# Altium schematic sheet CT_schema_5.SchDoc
size 578 x 363 mm
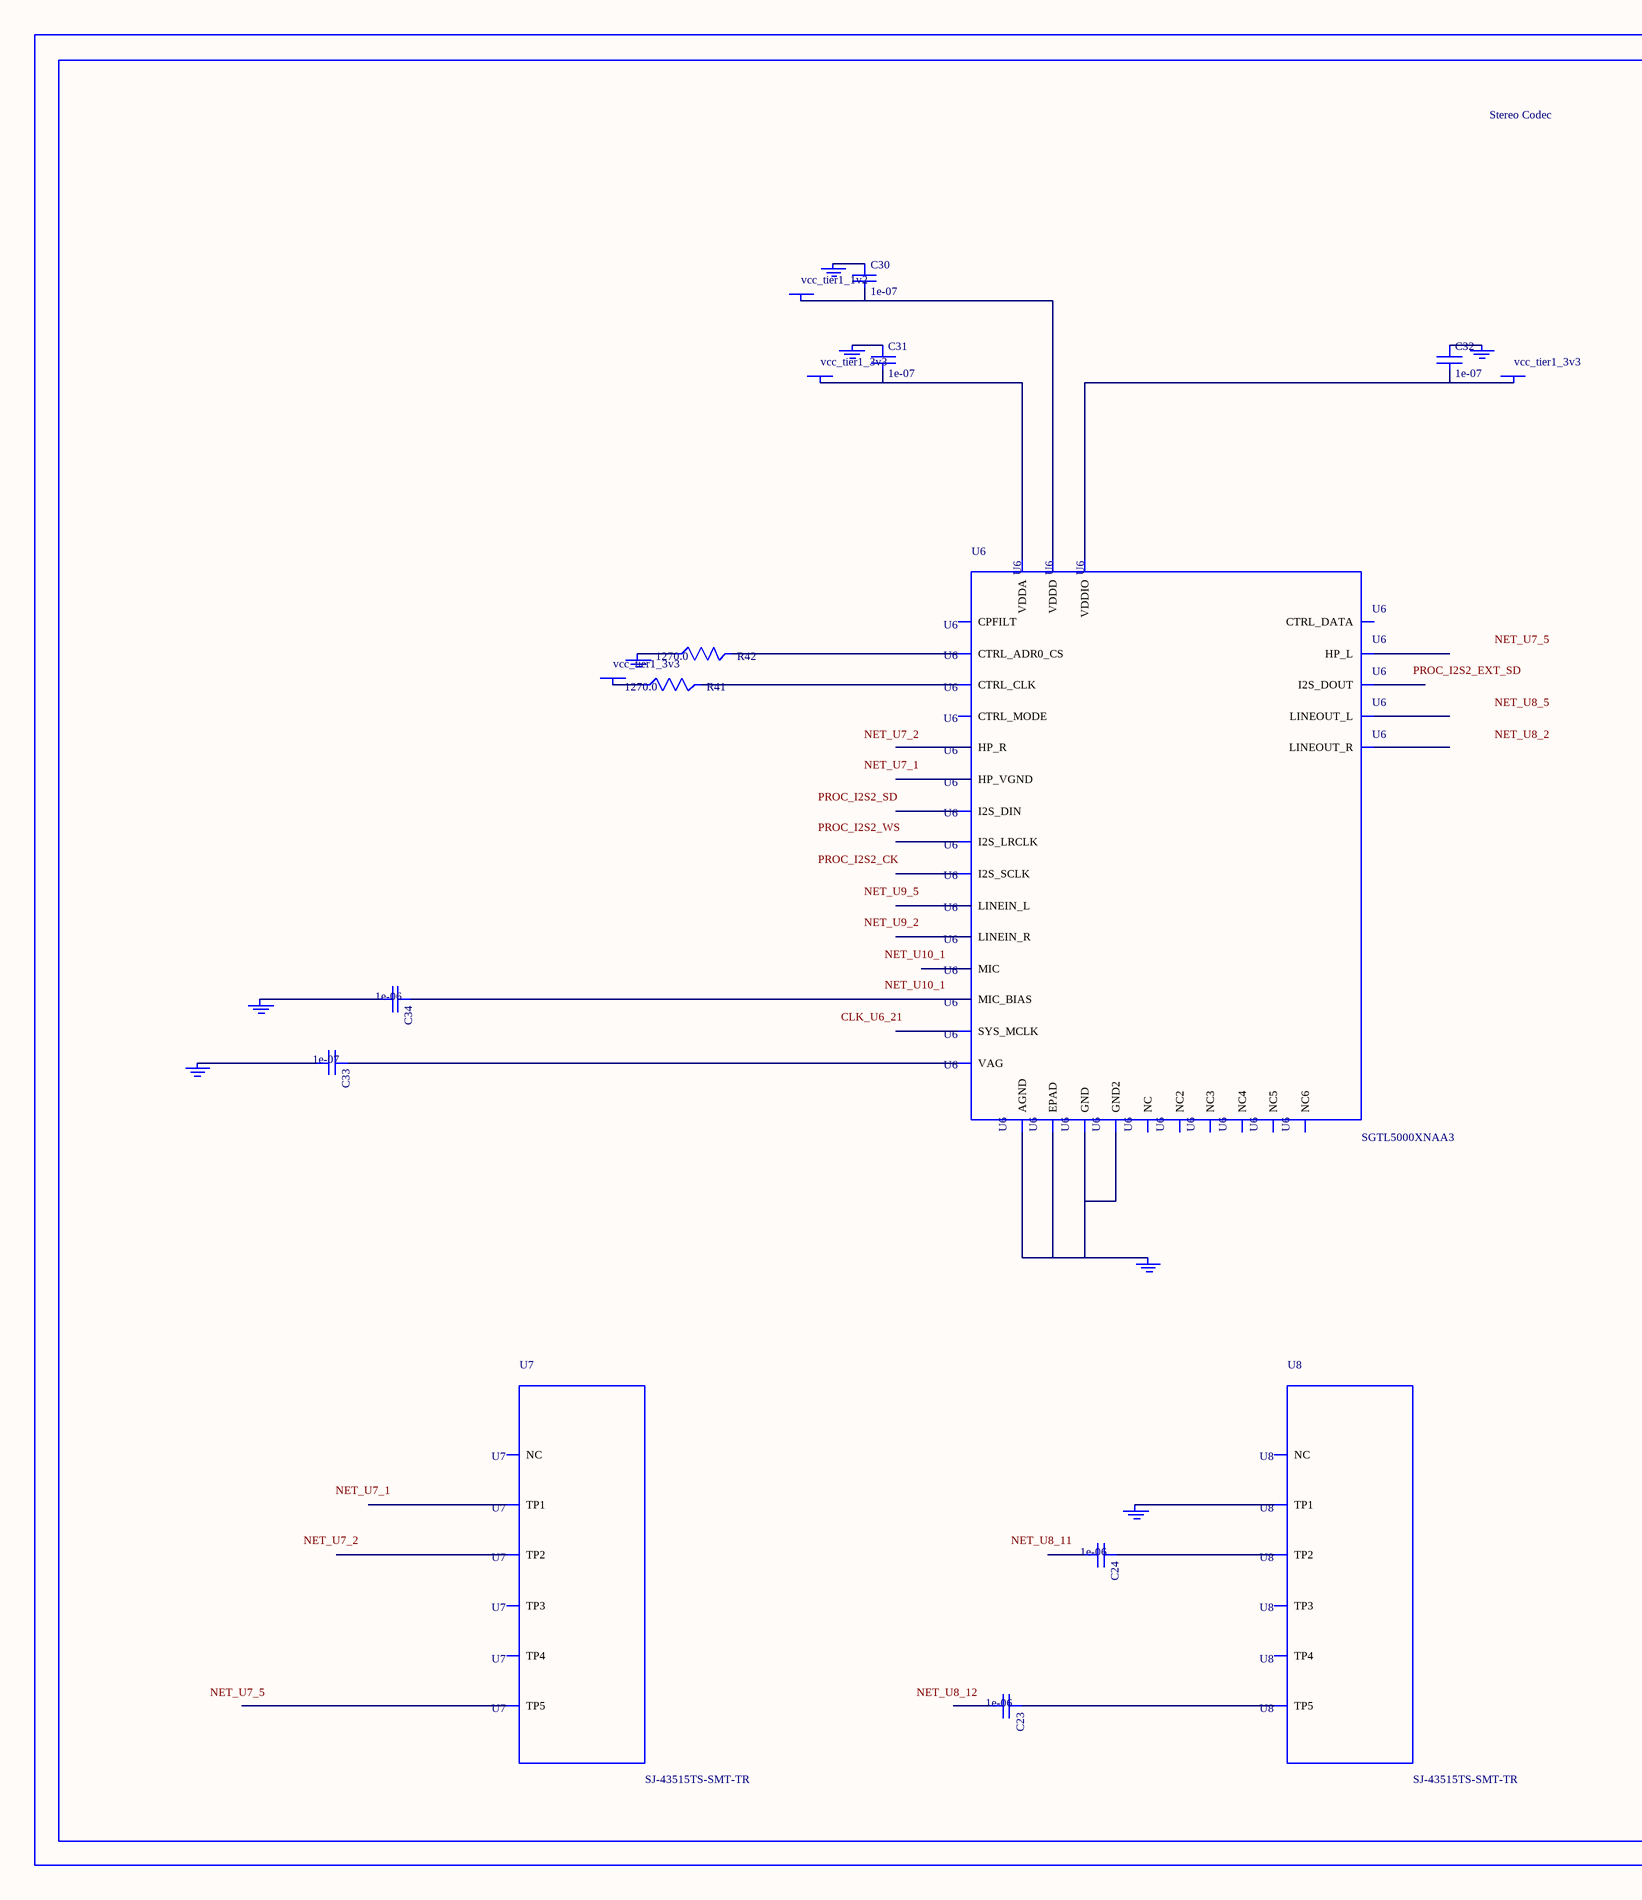
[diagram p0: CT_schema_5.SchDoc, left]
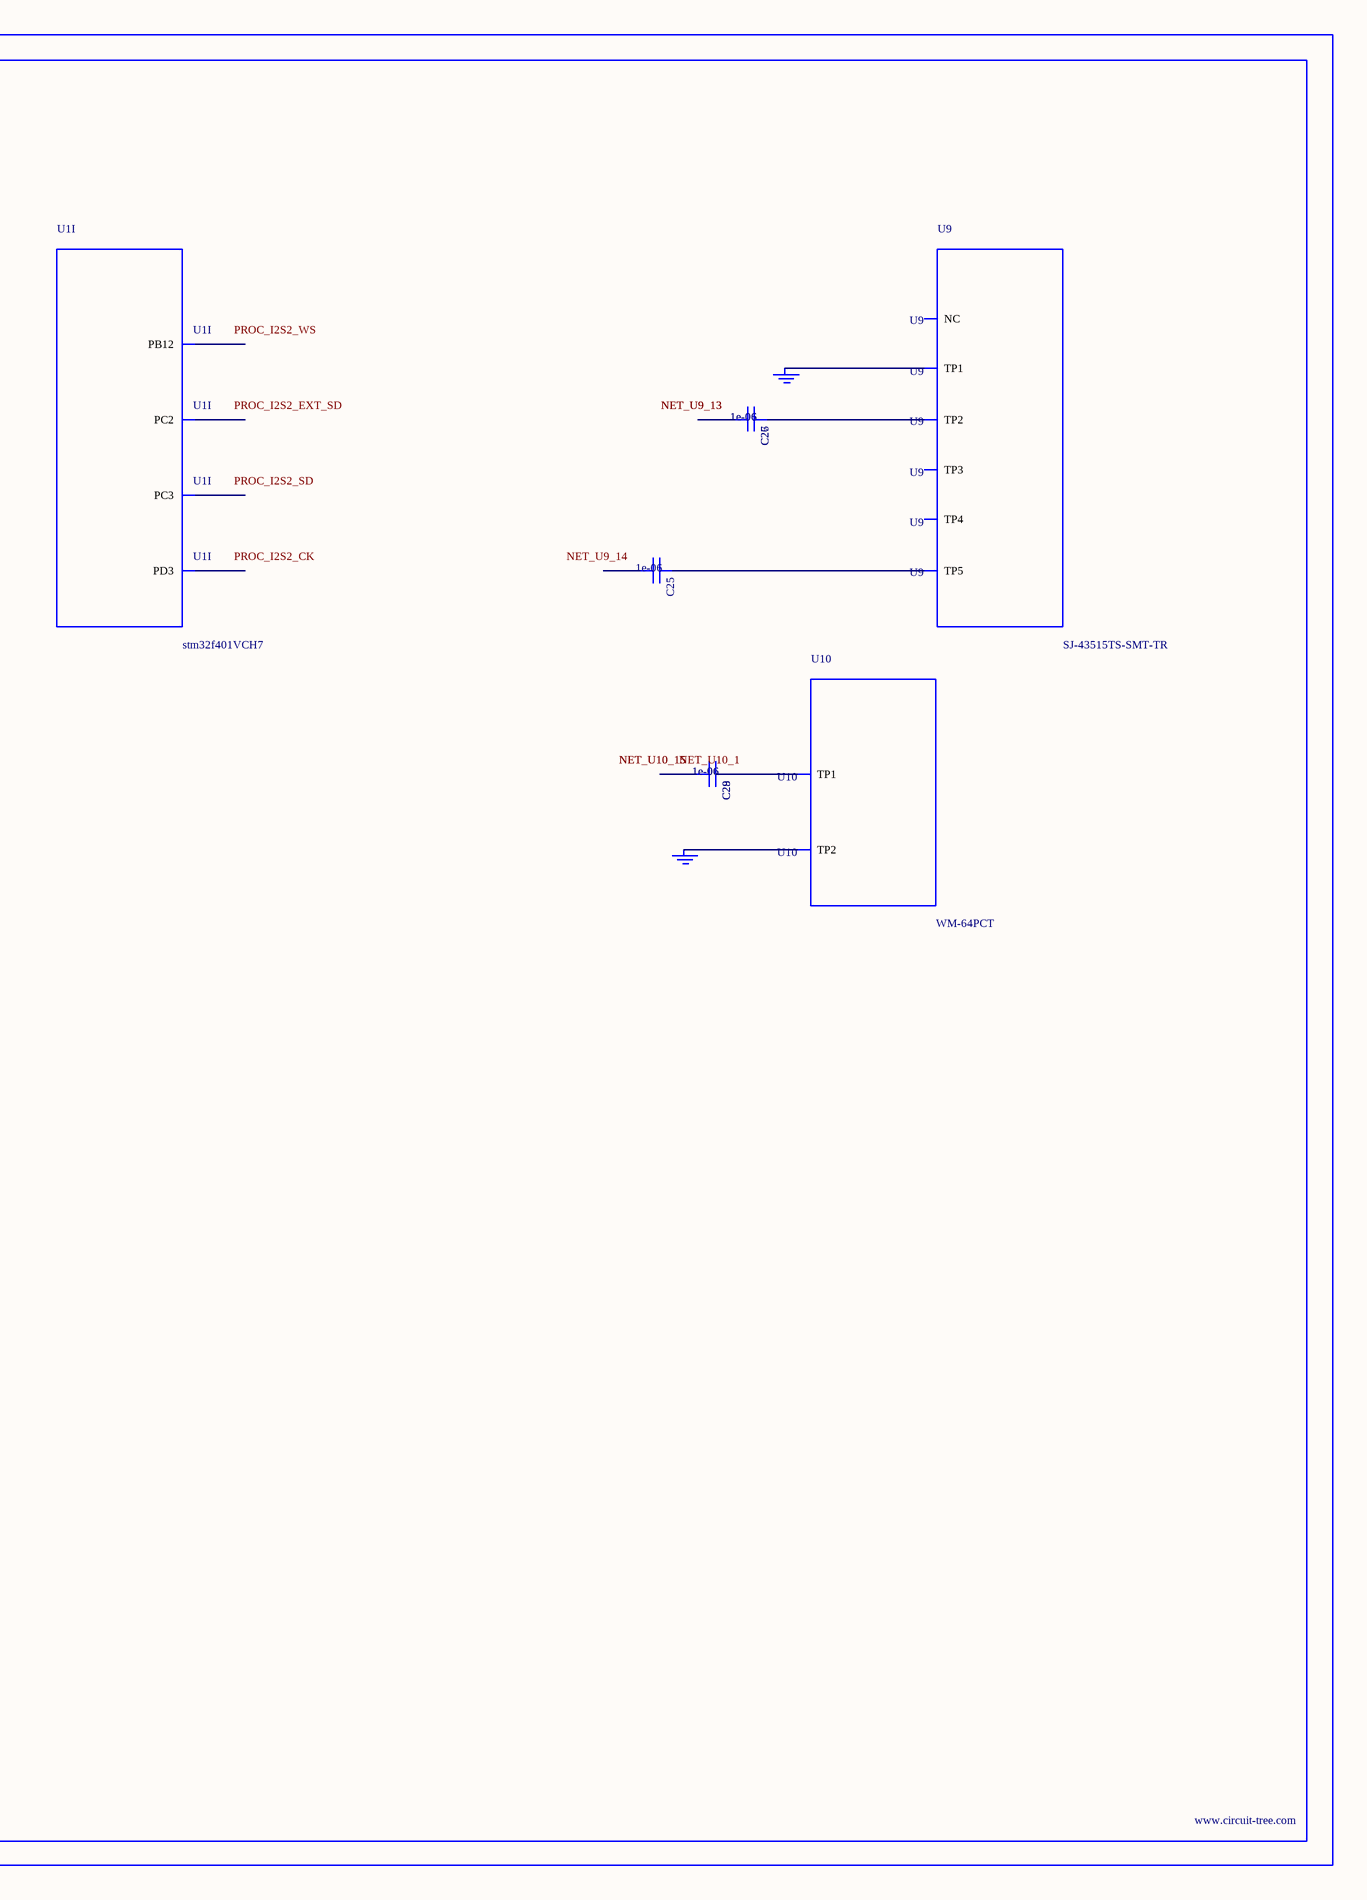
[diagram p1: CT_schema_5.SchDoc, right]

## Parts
BORDER4  (no value)
C23  1e-06  [C0603]
C24  1e-06  [C0603]
C25  1e-06  [C0603]
C26  1e-06  [C0603]
C27  1e-06  [C0603]
C28  1e-06  [C0603]
C29  1e-06  [C0603]
C30  1e-07  [C0402]
C31  1e-07  [C0402]
C32  1e-07  [C0402]
C33  1e-07  [C0402]
C34  1e-06  [C0603]
GND_INSTANCE_4_0  (no value)
GND_INSTANCE_4_1  (no value)
GND_INSTANCE_4_2  (no value)
GND_INSTANCE_4_3  (no value)
GND_INSTANCE_4_4  (no value)
GND_INSTANCE_4_5  (no value)
GND_INSTANCE_4_6  (no value)
GND_INSTANCE_4_7  (no value)
GND_INSTANCE_4_8  (no value)
GND_INSTANCE_4_9  (no value)
GND_INSTANCE_4_10  (no value)
POWER_INSTANCE_4_0  vcc_tier1_3v3
POWER_INSTANCE_4_1  vcc_tier1_3v3
POWER_INSTANCE_4_2  vcc_tier1_3v3
POWER_INSTANCE_4_3  vcc_tier1_1v2
R41  1270.0  [R0603]
R42  1270.0  [R0603]
U1  stm32f401VCH7  [UFBGA100]  (part I of 10)
U6  SGTL5000XNAA3  [QFN-32]
U7  SJ-43515TS-SMT-TR  [SJ-43515TS-SMT-TR]
U8  SJ-43515TS-SMT-TR  [SJ-43515TS-SMT-TR]
U9  SJ-43515TS-SMT-TR  [SJ-43515TS-SMT-TR]
U10  WM-64PCT  [WM-64PC]

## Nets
NetC23_1: C23.1 U8.5(TP5)
NetC24_1: C24.1 U8.2(TP2)
NetC25_1: C25.1 U9.5(TP5)
NetC26_1: C26.1 C27.1 U9.2(TP2)
NetC26_2: C26.2 C27.2
NetC28_1: C28.1 C29.1 U10.1(TP1)
NetC28_2: C28.2 C29.2
NetC30_1: C30.1 GND_INSTANCE_4_5.0(GND)
NetC30_2: C30.2 POWER_INSTANCE_4_3.0(PWR) U6.30(VDDD)
NetC31_1: C31.1 GND_INSTANCE_4_1.0(GND)
NetC31_2: C31.2 POWER_INSTANCE_4_0.0(PWR) U6.5(VDDA)
NetC32_1: C32.1 GND_INSTANCE_4_4.0(GND)
NetC32_2: C32.2 POWER_INSTANCE_4_1.0(PWR) U6.20(VDDIO)
NetC33_1: C33.1 U6.10(VAG)
NetC33_2: C33.2 GND_INSTANCE_4_2.0(GND)
NetC34_1: C34.1 U6.16(MIC_BIAS)
NetC34_2: C34.2 GND_INSTANCE_4_3.0(GND)
NetGND_INSTANCE_4_0_0: GND_INSTANCE_4_0.0(GND) U6.1(GND) U6.3(GND2) U6.7(AGND) U6.EXP(EPAD)
NetGND_INSTANCE_4_6_0: GND_INSTANCE_4_6.0(GND) R42.1
NetGND_INSTANCE_4_7_0: GND_INSTANCE_4_7.0(GND) U8.1(TP1)
NetGND_INSTANCE_4_8_0: GND_INSTANCE_4_8.0(GND) GND_INSTANCE_4_9.0(GND) U9.1(TP1)
NetGND_INSTANCE_4_10_0: GND_INSTANCE_4_10.0(GND) U10.2(TP2)
NetPOWER_INSTANCE_4_2_0: POWER_INSTANCE_4_2.0(PWR) R41.1
NetR41_2: R41.2 U6.29(CTRL_CLK)
NetR42_2: R42.2 U6.31(CTRL_ADR0_CS)

Not connected (* = marked no-connect by the designer): C23 2; C24 2; C25 2; U1 B8(PD3) J3(PC2) K2(PC3) L12(PB12); U6 2(HP_R) 4(HP_VGND) 6(HP_L) 8(NC) 9(NC2) 11(LINEOUT_R) 12(LINEOUT_L) 13(LINEIN_R) 14(LINEIN_L) 15(MIC) 17(NC3) 18(CPFILT) 19(NC4) 21(SYS_MCLK) 22(NC5) 23(I2S_LRCLK) 24(I2S_SCLK) 25(I2S_DOUT) 26(I2S_DIN) 27(CTRL_DATA) 28(NC6) 32(CTRL_MODE); U7 1(TP1) 2(TP2) 3(TP3) 4(TP4) 5(TP5) 6(NC); U8 3(TP3) 4(TP4) 6(NC); U9 3(TP3) 4(TP4) 6(NC)

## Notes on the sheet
- Labels drawn without touching a wire or pin: CLK_U6_21, NET_U7_1, NET_U7_2, NET_U7_5, NET_U8_2, NET_U8_5, NET_U8_11, NET_U8_12, NET_U9_2, NET_U9_5, NET_U9_14, NET_U10_1, PROC_I2S2_CK, PROC_I2S2_EXT_SD, PROC_I2S2_SD, PROC_I2S2_WS

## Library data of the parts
BORDER4 = BORDER_PAGE4
C23-C29 C34 = C0603C105K3RACTU
C30-C33 = C0402C104K3RACTU
GND_INSTANCE_4_0-GND_INSTANCE_4_10 = GND
POWER_INSTANCE_4_0-POWER_INSTANCE_4_3 = PWR
R41 R42 = RC0603FR-071K27L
